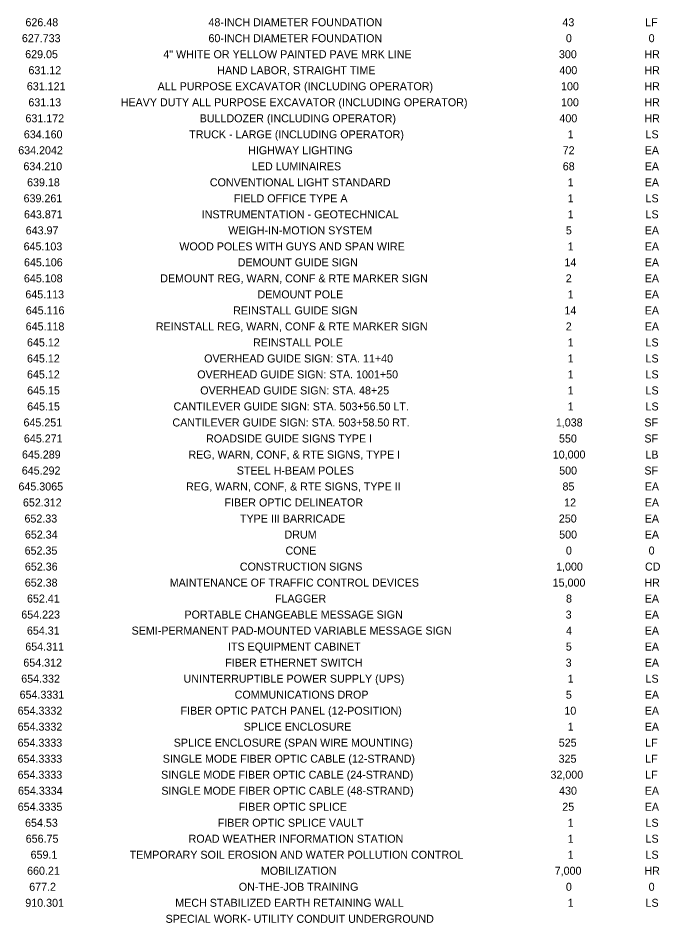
# Model space of a CAD drawing. Extents: x -18.7 to 5.6, y -2.7 to 5.1.
# Drawn here: x 0.023 to 0.812, y -2.684 to -1.571 of the extents above; entities that cross this region are included whole.
import ezdxf

# ---------------------------------------------------------------- set-up
doc = ezdxf.new("R2010")
doc.units = 0
doc.layers.add('ANNOTATION', color=7, linetype='Continuous')

msp = doc.modelspace()

# ---------------------------------------------------------------- texts
at = {"layer": 'ANNOTATION'}
for s, height, p in [('626.48', 0.00984, (0.0317, -1.5812)), ('48-INCH DIAMETER FOUNDATION', 0.009843, (0.2567, -1.5812)), ('43', 0.00984, (0.6919, -1.5812)), ('LF', 0.00984, (0.7937, -1.5812)), ('627.733', 0.00984, (0.0273, -1.6008)), ('60-INCH DIAMETER FOUNDATION', 0.009843, (0.2567, -1.6008)), ('0', 0.00984, (0.6962, -1.6008)), ('0', 0.00984, (0.7979, -1.6008)), ('629.05', 0.00984, (0.0314, -1.6205)), ('4" WHITE OR YELLOW PAINTED PAVE MRK LINE', 0.009843, (0.2012, -1.6205)), ('300', 0.00984, (0.6876, -1.6205)), ('HR', 0.00984, (0.7927, -1.6205)), ('631.12', 0.00984, (0.0354, -1.6402)), ('HAND LABOR, STRAIGHT TIME', 0.009843, (0.2675, -1.6402)), ('400', 0.00984, (0.6882, -1.6402)), ('HR', 0.00984, (0.7927, -1.6402)), ('631.121', 0.00984, (0.0334, -1.6599)), ('ALL PURPOSE EXCAVATOR (INCLUDING OPERATOR)', 0.009843, (0.1942, -1.6599)), ('100', 0.00984, (0.6902, -1.6599)), ('HR', 0.00984, (0.7927, -1.6599)), ('631.13', 0.00984, (0.0353, -1.6796)), ('HEAVY DUTY ALL PURPOSE EXCAVATOR (INCLUDING OPERATOR)', 0.009843, (0.1488, -1.6796)), ('100', 0.00984, (0.6902, -1.6796)), ('HR', 0.00984, (0.7927, -1.6796)), ('631.172', 0.00984, (0.0317, -1.6993)), ('BULLDOZER (INCLUDING OPERATOR)', 0.009843, (0.2459, -1.6993)), ('400', 0.00984, (0.6882, -1.6993)), ('HR', 0.00984, (0.7927, -1.6993)), ('634.160', 0.00984, (0.0297, -1.719)), ('TRUCK - LARGE (INCLUDING OPERATOR)', 0.009843, (0.233, -1.719)), ('1', 0.00984, (0.6984, -1.719)), ('LS', 0.00984, (0.7941, -1.719)), ('634.2042', 0.00984, (0.0228, -1.7386)), ('HIGHWAY LIGHTING', 0.009843, (0.3055, -1.7386)), ('72', 0.00984, (0.6922, -1.7386)), ('EA', 0.00984, (0.7931, -1.7386)), ('634.210', 0.00984, (0.0292, -1.7583)), ('LED LUMINAIRES', 0.009843, (0.3101, -1.7583)), ('68', 0.00984, (0.6923, -1.7583)), ('EA', 0.00984, (0.7931, -1.7583)), ('639.18', 0.00984, (0.0337, -1.778)), ('CONVENTIONAL LIGHT STANDARD', 0.009843, (0.2584, -1.778)), ('1', 0.00984, (0.6984, -1.778)), ('EA', 0.00984, (0.7931, -1.778)), ('639.261', 0.00984, (0.0294, -1.7977)), ('FIELD OFFICE TYPE A', 0.009843, (0.288, -1.7977)), ('1', 0.00984, (0.6984, -1.7977)), ('LS', 0.00984, (0.7941, -1.7977)), ('643.871', 0.00984, (0.0299, -1.8174)), ('INSTRUMENTATION - GEOTECHNICAL', 0.009843, (0.2484, -1.8174)), ('1', 0.00984, (0.6984, -1.8174)), ('LS', 0.00984, (0.7941, -1.8174)), ('643.97', 0.00984, (0.032, -1.8371)), ('WEIGH-IN-MOTION SYSTEM', 0.009843, (0.2811, -1.8371)), ('5', 0.00984, (0.6961, -1.8371)), ('EA', 0.00984, (0.7931, -1.8371)), ('645.103', 0.00984, (0.0294, -1.8568)), ('WOOD POLES WITH GUYS AND SPAN WIRE', 0.009843, (0.2209, -1.8568)), ('1', 0.00984, (0.6984, -1.8568)), ('EA', 0.00984, (0.7931, -1.8568)), ('645.106', 0.00984, (0.0299, -1.8764)), ('DEMOUNT GUIDE SIGN', 0.009843, (0.2926, -1.8764)), ('14', 0.00984, (0.6944, -1.8764)), ('EA', 0.00984, (0.7931, -1.8764)), ('645.108', 0.00984, (0.0298, -1.8961)), ('DEMOUNT REG, WARN, CONF & RTE MARKER SIGN', 0.009843, (0.1974, -1.8961)), ('2', 0.00984, (0.696, -1.8961)), ('EA', 0.00984, (0.7931, -1.8961)), ('645.113', 0.00984, (0.0316, -1.9158)), ('DEMOUNT POLE', 0.009843, (0.317, -1.9158)), ('1', 0.00984, (0.6984, -1.9158)), ('EA', 0.00984, (0.7931, -1.9158)), ('645.116', 0.00984, (0.0321, -1.9355)), ('REINSTALL GUIDE SIGN', 0.009843, (0.2871, -1.9355)), ('14', 0.00984, (0.6944, -1.9355)), ('EA', 0.00984, (0.7931, -1.9355)), ('645.118', 0.00984, (0.032, -1.9552)), ('REINSTALL REG, WARN, CONF & RTE MARKER SIGN', 0.009843, (0.192, -1.9552)), ('2', 0.00984, (0.696, -1.9552)), ('EA', 0.00984, (0.7931, -1.9552)), ('645.12', 0.00984, (0.0336, -1.9749)), ('REINSTALL POLE', 0.009843, (0.3115, -1.9749)), ('1', 0.00984, (0.6984, -1.9749)), ('LS', 0.00984, (0.7941, -1.9749)), ('645.12', 0.00984, (0.0336, -1.9946)), ('OVERHEAD GUIDE SIGN: STA. 11+40', 0.009843, (0.2514, -1.9946)), ('1', 0.00984, (0.6984, -1.9946)), ('LS', 0.00984, (0.7941, -1.9946)), ('645.12', 0.00984, (0.0336, -2.0142)), ('OVERHEAD GUIDE SIGN: STA. 1001+50', 0.009843, (0.2429, -2.0142)), ('1', 0.00984, (0.6984, -2.0142)), ('LS', 0.00984, (0.7941, -2.0142)), ('645.15', 0.00984, (0.0338, -2.0339)), ('OVERHEAD GUIDE SIGN: STA. 48+25', 0.009843, (0.2466, -2.0339)), ('1', 0.00984, (0.6984, -2.0339)), ('LS', 0.00984, (0.7941, -2.0339)), ('645.15', 0.00984, (0.0338, -2.0536)), ('CANTILEVER GUIDE SIGN: STA. 503+56.50 LT.', 0.009843, (0.2138, -2.0536)), ('1', 0.00984, (0.6984, -2.0536)), ('LS', 0.00984, (0.7941, -2.0536)), ('645.251', 0.00984, (0.0293, -2.0733)), ('CANTILEVER GUIDE SIGN: STA. 503+58.50 RT.', 0.009843, (0.2124, -2.0733)), ('1,038', 0.00984, (0.6838, -2.0733)), ('SF', 0.00984, (0.7927, -2.0733)), ('645.271', 0.00984, (0.0298, -2.093)), ('ROADSIDE GUIDE SIGNS TYPE I ', 0.009843, (0.2538, -2.093)), ('550', 0.00984, (0.6877, -2.093)), ('SF', 0.00984, (0.7927, -2.093)), ('645.289', 0.00984, (0.0274, -2.1127)), ('REG, WARN, CONF, & RTE SIGNS, TYPE I', 0.009843, (0.232, -2.1127)), ('10,000', 0.00984, (0.68, -2.1127)), ('LB', 0.00984, (0.7939, -2.1127)), ('645.292', 0.00984, (0.0272, -2.1324)), ('STEEL H-BEAM POLES', 0.009843, (0.2915, -2.1324)), ('500', 0.00984, (0.6879, -2.1324)), ('SF', 0.00984, (0.7927, -2.1324)), ('645.3065', 0.00984, (0.0231, -2.152)), ('REG, WARN, CONF, & RTE SIGNS, TYPE II', 0.009843, (0.2291, -2.152)), ('85', 0.00984, (0.692, -2.152)), ('EA', 0.00984, (0.7931, -2.152)), ('652.312', 0.00984, (0.0286, -2.1717)), ('FIBER OPTIC DELINEATOR', 0.009843, (0.2764, -2.1717)), ('12', 0.00984, (0.694, -2.1717)), ('EA', 0.00984, (0.7931, -2.1717)), ('652.33', 0.00984, (0.0305, -2.1914)), ('TYPE III BARRICADE', 0.009843, (0.2954, -2.1914)), ('250', 0.00984, (0.6875, -2.1914)), ('EA', 0.00984, (0.7931, -2.1914)), ('652.34', 0.00984, (0.031, -2.2111)), ('DRUM', 0.00984, (0.3502, -2.2111)), ('500', 0.00984, (0.6879, -2.2111)), ('EA', 0.00984, (0.7931, -2.2111)), ('652.35', 0.00984, (0.0307, -2.2308)), ('CONE', 0.00984, (0.3514, -2.2308)), ('0', 0.00984, (0.6962, -2.2308)), ('0', 0.00984, (0.7979, -2.2308)), ('652.36', 0.00984, (0.031, -2.2505)), ('CONSTRUCTION SIGNS', 0.009843, (0.2953, -2.2505)), ('1,000', 0.00984, (0.6841, -2.2505)), ('CD', 0.00984, (0.7934, -2.2505)), ('652.38', 0.00984, (0.0309, -2.2702)), ('MAINTENANCE OF TRAFFIC CONTROL DEVICES', 0.009843, (0.2091, -2.2702)), ('15,000', 0.00984, (0.6799, -2.2702)), ('HR', 0.00984, (0.7927, -2.2702)), ('652.41', 0.00984, (0.0336, -2.2898)), ('FLAGGER', 0.00984, (0.3385, -2.2898)), ('8', 0.00984, (0.6963, -2.2898)), ('EA', 0.00984, (0.7931, -2.2898)), ('654.223', 0.00984, (0.0266, -2.3095)), ('PORTABLE CHANGEABLE MESSAGE SIGN', 0.009843, (0.2272, -2.3095)), ('3', 0.00984, (0.6959, -2.3095)), ('EA', 0.00984, (0.7931, -2.3095)), ('654.31', 0.00984, (0.0335, -2.3292)), ('SEMI-PERMANENT PAD-MOUNTED VARIABLE MESSAGE SIGN', 0.009843, (0.1622, -2.3292)), ('4', 0.00984, (0.6964, -2.3292)), ('EA', 0.00984, (0.7931, -2.3292)), ('654.311', 0.00984, (0.0315, -2.3489)), ('ITS EQUIPMENT CABINET', 0.009843, (0.2807, -2.3489)), ('5', 0.00984, (0.6961, -2.3489)), ('EA', 0.00984, (0.7931, -2.3489)), ('654.312', 0.00984, (0.0291, -2.3686)), ('FIBER ETHERNET SWITCH', 0.009843, (0.2773, -2.3686)), ('3', 0.00984, (0.6959, -2.3686)), ('EA', 0.00984, (0.7931, -2.3686)), ('654.332', 0.00984, (0.0265, -2.3883)), ('UNINTERRUPTIBLE POWER SUPPLY (UPS)', 0.009843, (0.2261, -2.3883)), ('1', 0.00984, (0.6984, -2.3883)), ('LS', 0.00984, (0.7941, -2.3883)), ('654.3331', 0.00984, (0.0245, -2.408)), ('COMMUNICATIONS DROP', 0.009843, (0.2889, -2.408)), ('5', 0.00984, (0.6961, -2.408)), ('EA', 0.00984, (0.7931, -2.408)), ('654.3332', 0.00984, (0.0221, -2.4277)), ('FIBER OPTIC PATCH PANEL (12-POSITION)', 0.009843, (0.2224, -2.4277)), ('10', 0.00984, (0.6943, -2.4277)), ('EA', 0.00984, (0.7931, -2.4277)), ('654.3332', 0.00984, (0.0221, -2.4473)), ('SPLICE ENCLOSURE', 0.009843, (0.3, -2.4473)), ('1', 0.00984, (0.6984, -2.4473)), ('EA', 0.00984, (0.7931, -2.4473)), ('654.3333', 0.00984, (0.022, -2.467)), ('SPLICE ENCLOSURE (SPAN WIRE MOUNTING)', 0.009843, (0.214, -2.467)), ('525', 0.00984, (0.6874, -2.467)), ('LF', 0.00984, (0.7937, -2.467)), ('654.3333', 0.00984, (0.022, -2.4867)), ('SINGLE MODE FIBER OPTIC CABLE (12-STRAND)', 0.009843, (0.2005, -2.4867)), ('325', 0.00984, (0.6872, -2.4867)), ('LF', 0.00984, (0.7937, -2.4867)), ('654.3333', 0.00984, (0.022, -2.5064)), ('SINGLE MODE FIBER OPTIC CABLE (24-STRAND)', 0.009843, (0.1985, -2.5064)), ('32,000', 0.00984, (0.6772, -2.5064)), ('LF', 0.00984, (0.7937, -2.5064)), ('654.3334', 0.00984, (0.0225, -2.5261)), ('SINGLE MODE FIBER OPTIC CABLE (48-STRAND)', 0.009843, (0.1988, -2.5261)), ('430', 0.00984, (0.6878, -2.5261)), ('EA', 0.00984, (0.7931, -2.5261)), ('654.3335', 0.00984, (0.0222, -2.5458)), ('FIBER OPTIC SPLICE', 0.009843, (0.2938, -2.5458)), ('25', 0.00984, (0.6917, -2.5458)), ('EA', 0.00984, (0.7931, -2.5458)), ('654.53', 0.00984, (0.0312, -2.5655)), ('FIBER OPTIC SPLICE VAULT', 0.009843, (0.2681, -2.5655)), ('1', 0.00984, (0.6984, -2.5655)), ('LS', 0.00984, (0.7941, -2.5655)), ('656.75', 0.00984, (0.032, -2.5851)), ('ROAD WEATHER INFORMATION STATION', 0.009843, (0.2323, -2.5851)), ('1', 0.00984, (0.6984, -2.5851)), ('LS', 0.00984, (0.7941, -2.5851)), ('659.1', 0.00984, (0.038, -2.6048)), ('TEMPORARY SOIL EROSION AND WATER POLLUTION CONTROL', 0.009843, (0.1598, -2.6048)), ('1', 0.00984, (0.6984, -2.6048)), ('LS', 0.00984, (0.7941, -2.6048)), ('660.21', 0.00984, (0.0337, -2.6245)), ('MOBILIZATION', 0.009843, (0.3212, -2.6245)), ('7,000', 0.00984, (0.6824, -2.6245)), ('HR', 0.00984, (0.7927, -2.6245)), ('677.2', 0.00984, (0.0363, -2.6442)), ('ON-THE-JOB TRAINING', 0.009843, (0.294, -2.6442)), ('0', 0.00984, (0.6962, -2.6442)), ('0', 0.00984, (0.7979, -2.6442)), ('910.301', 0.00984, (0.0315, -2.6639)), ('MECH STABILIZED EARTH RETAINING WALL', 0.009843, (0.2159, -2.6639)), ('1', 0.00984, (0.6984, -2.6639)), ('LS', 0.00984, (0.7941, -2.6639)), ('SPECIAL WORK- UTILITY CONDUIT UNDERGROUND', 0.009843, (0.204, -2.6836))]:
    msp.add_text(s, height=height, dxfattribs=at).set_placement(p)

doc.saveas('drawing.dxf')
